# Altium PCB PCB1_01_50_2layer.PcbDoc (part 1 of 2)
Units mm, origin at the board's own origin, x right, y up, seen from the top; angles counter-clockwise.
Board outline 28.45 x 21.72 mm, 2 copper layers (Top Layer, Bottom Layer); 0 components, 1 nets, 10 pads, 74 vias.
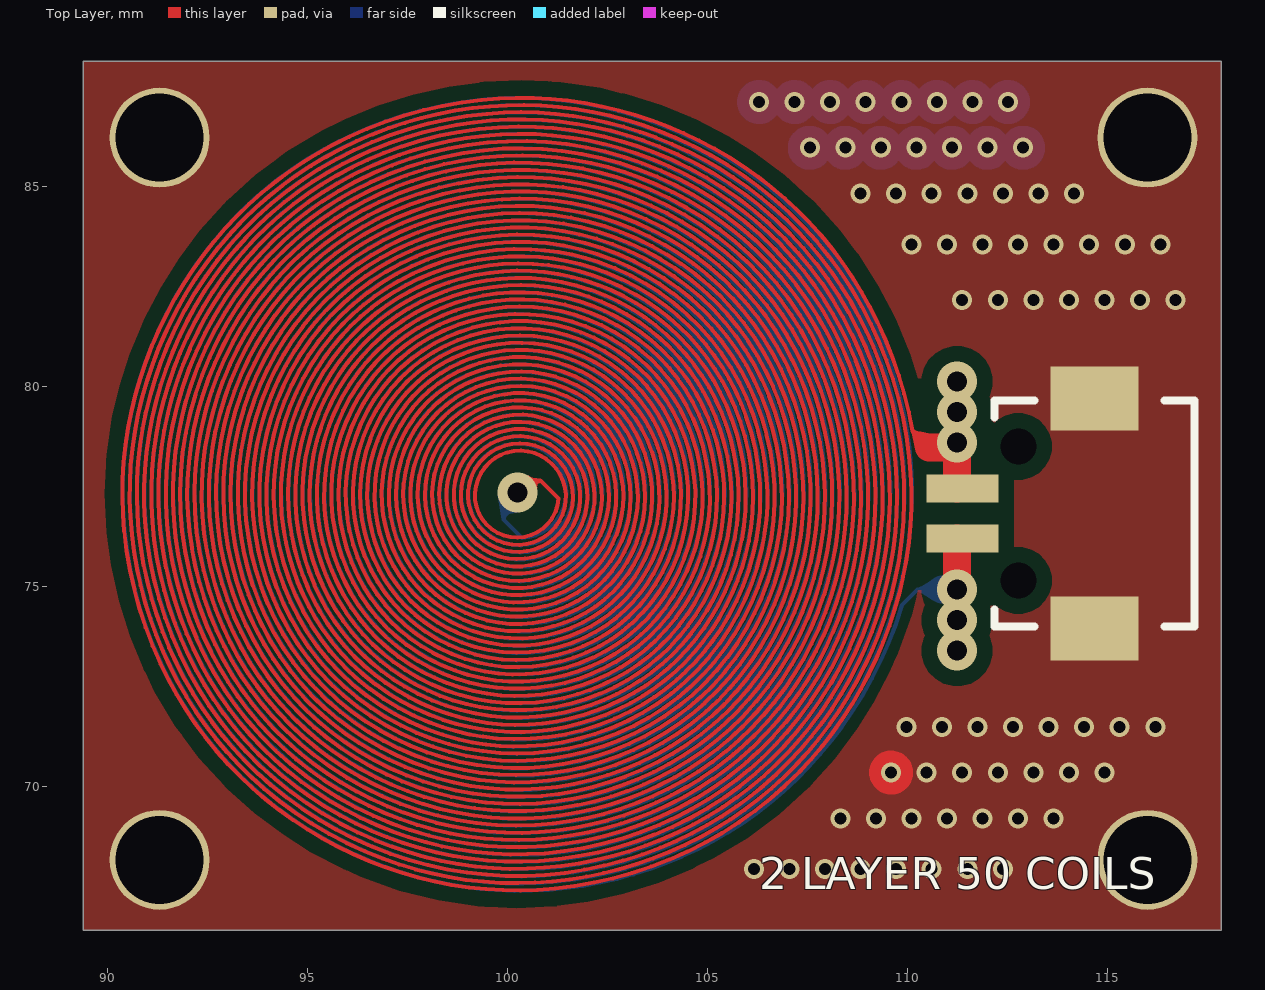
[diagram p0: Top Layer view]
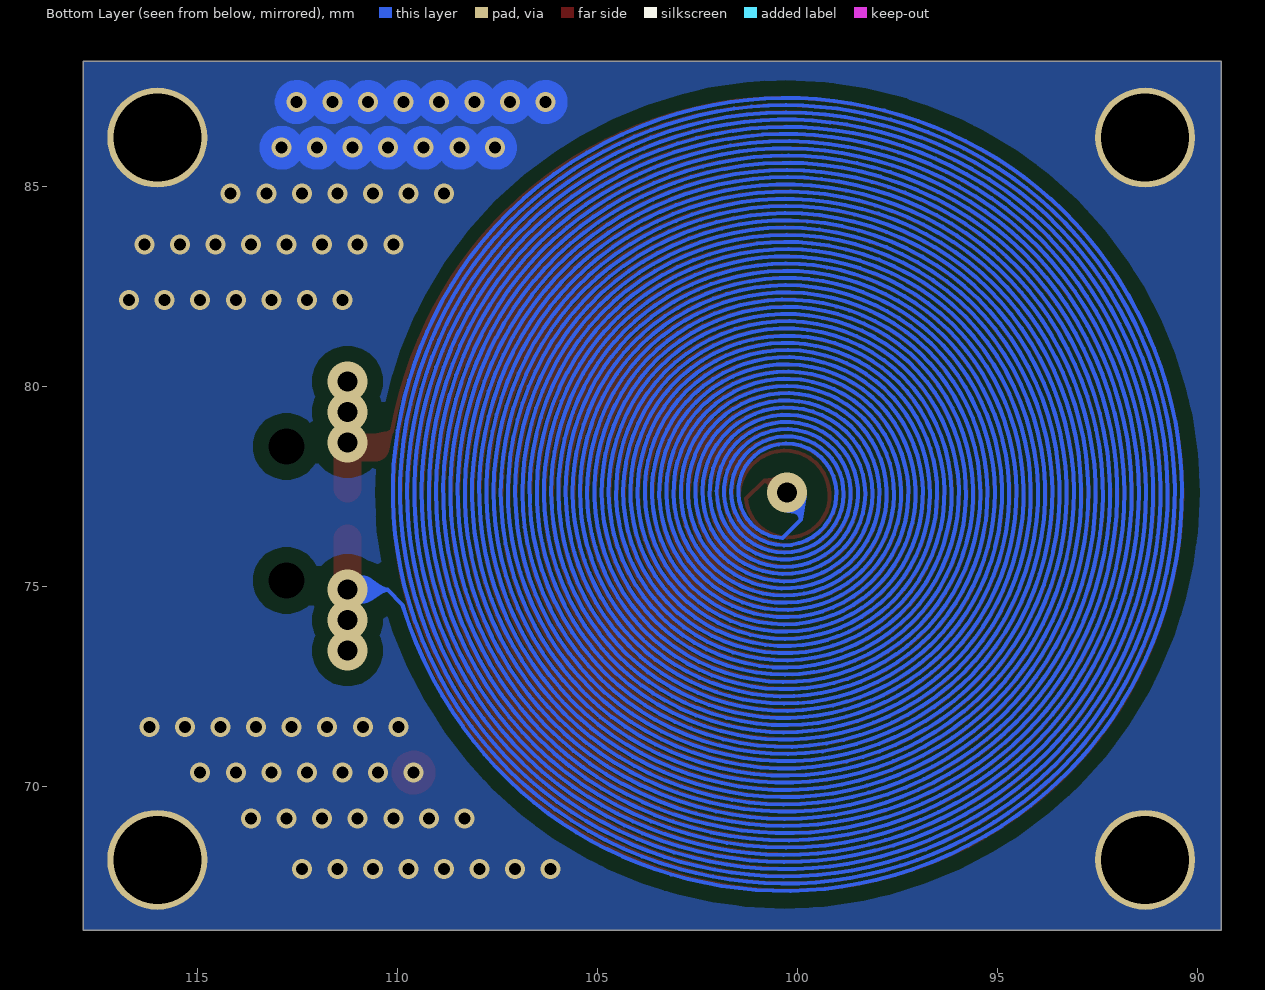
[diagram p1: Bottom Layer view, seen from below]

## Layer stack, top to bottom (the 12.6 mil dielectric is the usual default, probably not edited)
Top Solder: solder mask 0.0102, Solder Resist, Dk 3.5
Top Layer: signal copper 0.0356
Dielectric 1: dielectric 0.32, FR-4, Dk 4.8
Bottom Layer: signal copper 0.0356
Bottom Solder: solder mask 0.0102, Solder Resist, Dk 3.5

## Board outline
89.408,66.421 89.408,88.138 117.856,88.138 117.856,66.421

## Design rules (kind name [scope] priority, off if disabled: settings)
Clearance [All] p1: gap=0.381 ignorepadtopadclearanceinfootprint=FALSE
PolygonConnect [All] p1: connectstyle=Direct reliefconductorwidth=0.254 reliefentries=4 polygonreliefangle="90 Angle" airgapwidth=0.254
RoutingVias [All] p1: holewidth=0.711 width=1.27 viastyle="Through Hole" minholewidth=0.711 minwidth=1.27 maxholewidth=0.711 maxwidth=1.27
SolderMaskExpansion [All] p1: expansion=0.102 istentingtop=FALSE
Width Width_1 [All] p1: maxlimit=0.8 minlimit=0.1 preferedwidth=0.1 minimp=50.000000 maximp=50.000000 favimp=50.000000
Width [All] p2: maxlimit=0.254 minlimit=0.254 preferedwidth=0.254
30 further rules are at their usual default settings.

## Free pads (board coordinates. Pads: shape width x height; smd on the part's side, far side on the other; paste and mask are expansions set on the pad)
  round 2.5 hole 2.2: 1(91.313,68.177) 1(91.313,86.233) 1(116.008,86.233) 1(116.008,68.177)
  rect 1.8x0.7 smd: 1(111.381,77.46) 2(111.381,76.21)
  round 0.45 hole 0.9 unplated: MH1(112.781,78.51) MH2(112.781,75.16)
  rect 2.2x1.6 smd: MP1(114.681,79.71) MP2(114.681,73.96)

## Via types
v1: diameter 0.5, hole 0.3, Top Layer to Bottom Layer, tented both sides, 67 vias
v2: diameter 1, hole 0.5, Top Layer to Bottom Layer, 7 vias

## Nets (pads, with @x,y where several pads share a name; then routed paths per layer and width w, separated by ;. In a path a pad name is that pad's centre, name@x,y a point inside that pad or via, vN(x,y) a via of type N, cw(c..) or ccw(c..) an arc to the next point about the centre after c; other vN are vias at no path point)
Net1: pad.1@91.313,68.177 pad.1@91.313,86.233 pad.1@116.008,68.177 pad.1@116.008,86.233 pad.MP1 pad.MP2 | length 25.1
  Top Layer w0.6: 109.851,70.358 ccw(c109.601,70.358) 109.851,70.358
  Bottom Layer w0.6: 106.549,87.122 ccw(c106.299,87.122) 106.549,87.122 ; 107.438,87.122 ccw(c107.188,87.122) 107.438,87.122 ; 107.819,85.979 ccw(c107.569,85.979) 107.819,85.979 ; 108.327,87.122 ccw(c108.077,87.122) 108.327,87.122 ; 108.708,85.979 ccw(c108.458,85.979) 108.708,85.979 ; 109.216,87.122 ccw(c108.966,87.122) 109.216,87.122 ; 109.597,85.979 ccw(c109.347,85.979) 109.597,85.979 ; 110.105,87.122 ccw(c109.855,87.122) 110.105,87.122 ; 110.486,85.979 ccw(c110.236,85.979) 110.486,85.979 ; 110.994,87.122 ccw(c110.744,87.122) 110.994,87.122 ; 111.375,85.979 ccw(c111.125,85.979) 111.375,85.979 ; 111.883,87.122 ccw(c111.633,87.122) 111.883,87.122 ; 112.264,85.979 ccw(c112.014,85.979) 112.264,85.979 ; 112.772,87.122 ccw(c112.522,87.122) 112.772,87.122 ; 113.153,85.979 ccw(c112.903,85.979) 113.153,85.979
  other v1: 106.172,67.945 107.061,67.945 107.95,67.945 108.839,67.945 109.728,67.945 110.617,67.945 111.506,67.945 112.395,67.945 108.331,69.215 109.22,69.215 110.109,69.215 110.998,69.215 111.887,69.215 112.776,69.215 113.665,69.215 109.601,70.358 110.49,70.358 111.379,70.358 112.268,70.358 113.157,70.358 114.046,70.358 114.935,70.358 109.982,71.501 110.871,71.501 111.76,71.501 112.649,71.501 113.538,71.501 114.427,71.501 115.316,71.501 116.205,71.501 111.379,82.169 112.268,82.169 113.157,82.169 114.046,82.169 114.935,82.169 115.824,82.169 116.713,82.169 110.109,83.566 110.998,83.566 111.887,83.566 112.776,83.566 113.665,83.566 114.554,83.566 115.443,83.566 116.332,83.566 108.839,84.836 109.728,84.836 110.617,84.836 111.506,84.836 112.395,84.836 113.284,84.836 114.173,84.836 107.569,85.979 108.458,85.979 109.347,85.979 110.236,85.979 111.125,85.979 112.014,85.979 112.903,85.979 106.299,87.122 107.188,87.122 108.077,87.122 108.966,87.122 109.855,87.122 110.744,87.122 111.633,87.122 112.522,87.122
copper on no net: | length 3452.1
  Top Layer w0.1: v2(100.265,77.355) 100.563,77.653 100.843,77.653 101.289,77.207 cw(c100.244,77.281) 99.224,77.518 cw(c100.317,77.292) 100.518,78.39 cw(c100.31,77.249) 101.464,77.134 cw(c100.269,77.253) 100.309,76.052 cw(c100.267,77.293) 99.054,77.03 cw(c100.306,77.302) 99.763,78.462 cw(c100.322,77.268) 101.332,78.116 cw(c100.294,77.245) 101.43,76.506 cw(c100.261,77.266) 99.925,75.913 cw(c100.267,77.295) 98.853,77.133 cw(c100.309,77.299) 99.599,78.58 cw(c100.322,77.279) 101.227,78.461 cw(c100.296,77.244) 101.795,76.927 cw(c100.276,77.249) 100.66,75.744 cw(c100.262,77.287) 99.085,76.213 cw(c100.29,77.304) 98.75,77.824 cw(c100.306,77.303) 99.989,78.913 cw(c100.319,77.259) 101.56,78.402 cw(c100.289,77.245) 101.948,76.794 cw(c100.279,77.246) 100.801,75.598 cw(c100.259,77.272) 99.168,75.891 cw(c100.29,77.308) 98.486,77.406 cw(c100.317,77.293) 99.329,78.839 cw(c100.319,77.283) 100.986,79.002 cw(c100.325,77.266) 102.112,77.774 cw(c100.271,77.247) 100.359,75.334 cw(c100.271,77.305) 98.815,75.974 cw(c100.304,77.309) 98.321,77.573 cw(c100.318,77.291) 99.222,78.984 cw(c100.32,77.277) 100.88,79.228 cw(c100.32,77.264) 102.161,78.147 cw(c100.312,77.246) 102.217,76.471 cw(c100.289,77.235) 101.022,75.295 cw(c100.26,77.247) 99.344,75.362 cw(c100.249,77.277) 98.235,76.624 cw(c100.262,77.306) 98.367,78.299 cw(c100.293,77.318) 99.654,79.383 cw(c100.323,77.305) 101.33,79.241 cw(c100.336,77.275) 102.429,77.966 cw(c100.278,77.246) 101.102,75.133 cw(c100.262,77.286) 98.18,76.282 cw(c100.313,77.303) 100.72,79.634 cw(c100.299,77.229) 102.181,78.783 cw(c100.292,77.244) 102.101,75.61 cw(c100.26,77.274) 100.606,74.817 cw(c100.26,77.265) 98.951,75.168 cw(c100.24,77.271) 97.899,76.493 cw(c100.304,77.304) 99.008,79.486 cw(c100.326,77.257) 100.669,79.824 cw(c100.314,77.255) 102.894,77.515 cw(c100.296,77.246) 102.512,75.863 cw(c100.301,77.217) 101.203,74.787 cw(c100.26,77.285) 98.116,75.693 cw(c100.286,77.304) 98.118,78.918 cw(c100.292,77.32) 99.502,79.9 cw(c100.321,77.261) 102.566,78.872 cw(c100.298,77.245) 102.576,75.632 cw(c100.3,77.218) 101.224,74.603 cw(c100.261,77.232) 99.527,74.53 cw(c100.285,77.326) 98.088,75.439 cw(c100.33,77.32) 97.42,77.005 cw(c100.268,77.306) 97.751,78.672 cw(c100.322,77.286) 100.63,80.191 cw(c100.292,77.208) 102.199,79.527 cw(c100.328,77.269) 103.138,78.108 cw(c100.351,77.244) 103.146,76.406 cw(c100.239,77.269) 102.222,74.975 cw(c100.246,77.313) 100.665,74.28 cw(c100.257,77.228) 98.983,74.539 cw(c100.242,77.269) 97.702,75.661 cw(c100.345,77.323) 97.223,77.298 cw(c100.313,77.293) 97.696,78.936 cw(c100.324,77.281) 100.642,80.371 cw(c100.292,77.207) 102.226,79.735 cw(c100.353,77.288) 103.24,78.366 cw(c100.319,77.243) 103.395,76.669 cw(c100.28,77.248) 101.206,74.217 cw(c100.26,77.216) 99.502,74.165 cw(c100.298,77.351) 98.009,74.995 cw(c100.284,77.297) 97.155,76.472 cw(c100.217,77.306) 97.165,78.177 cw(c100.363,77.27) 98.037,79.645 cw(c100.32,77.269) 99.533,80.469 cw(c100.321,77.26) 102.701,79.552 cw(c100.285,77.246) 103.526,78.057 cw(c100.371,77.242) 103.505,76.351 cw(c100.214,77.281) 102.643,74.875 cw(c100.269,77.268) 101.166,74.018 cw(c100.26,77.203) 99.459,73.99 cw(c100.301,77.36) 97.953,74.8 cw(c100.259,77.281) 97.036,76.241 cw(c100.244,77.306) 96.925,77.945 cw(c100.379,77.264) 97.653,79.493 cw(c100.273,77.341) 99.034,80.497 cw(c100.327,77.277) 100.728,80.723 cw(c100.288,77.201) 102.324,80.109 cw(c100.293,77.239) 103.808,77.143 cw(c100.268,77.259) 103.341,75.498 cw(c100.321,77.2) 102.161,74.263 cw(c100.265,77.26) 98.852,74.007 cw(c100.267,77.304) 97.486,75.036 cw(c100.339,77.322) 96.758,76.585 cw(c100.306,77.304) 97.668,79.782 cw(c100.291,77.314) 99.101,80.714 cw(c100.326,77.296) 100.802,80.895 cw(c100.285,77.195) 102.399,80.276 cw(c100.299,77.242) 103.987,77.351 cw(c100.322,77.247) 103.636,75.677 cw(c100.274,77.24) 102.575,74.334 cw(c100.242,77.328) 101.022,73.613 cw(c100.257,77.173) 99.313,73.656 cw(c100.307,77.373) 97.798,74.457 cw(c100.22,77.252) 96.799,75.846 cw(c100.319,77.318) 96.51,77.533 cw(c100.328,77.284) 97.001,79.174 cw(c100.265,77.347) 98.156,80.436 cw(c100.349,77.196) 99.751,81.063 cw(c100.317,77.252) 102.94,80.074 cw(c100.345,77.286) 103.899,78.656 cw(c100.274,77.233) 104.159,76.963 cw(c100.247,77.268) 103.656,75.325 cw(c100.317,77.202) 102.505,74.058 cw(c100.233,77.352) 100.918,73.41 cw(c100.262,77.288) 97.697,74.306 cw(c100.207,77.24) 96.675,75.68 cw(c100.347,77.325) 96.323,77.358 cw(c100.281,77.296) 96.72,79.024 cw(c100.314,77.307) 97.774,80.375 cw(c100.333,77.235) 99.302,81.152 cw(c100.324,77.35) 101.012,81.226 cw(c100.277,77.178) 102.599,80.575 cw(c100.399,77.333) 103.771,79.328 cw(c100.302,77.248) 104.149,75.999 cw(c100.191,77.292) 103.292,74.513 cw(c100.319,77.199) 101.899,73.517 cw(c100.24,77.331) 100.219,73.172 cw(c100.268,77.254) 98.548,73.552 cw(c100.272,77.316) 97.171,74.573 cw(c100.305,77.303) 96.335,76.07 cw(c100.26,77.311) 96.17,77.776 cw(c100.358,77.272) 96.717,79.402 cw(c100.263,77.351) 97.866,80.673 cw(c100.347,77.2) 99.435,81.369 cw(c100.325,77.381) 101.148,81.384 cw(c100.272,77.168) 102.725,80.706 cw(c100.405,77.338) 103.901,79.461 cw(c100.194,77.211) 104.484,77.846 cw(c100.269,77.252) 102.289,73.506 cw(c100.228,77.372) 100.645,73.01 cw(c100.253,77.156) 98.943,73.203 cw(c100.314,77.384) 97.447,74.047 cw(c100.189,77.225) 96.405,75.407 cw(c100.38,77.335) 95.971,77.068 cw(c100.194,77.31) 96.221,78.763 cw(c100.393,77.256) 97.106,80.235 cw(c100.253,77.362) 98.492,81.242 cw(c100.349,77.193) 100.162,81.644 cw(c100.325,77.358) 101.853,81.365 cw(c100.275,77.177) 103.314,80.463 cw(c100.373,77.309) 104.311,79.068 cw(c100.21,77.216) 104.706,77.397 cw(c100.376,77.241) 104.427,75.705 cw(c100.19,77.292) 103.53,74.24 cw(c100.331,77.185) 102.144,73.233 cw(c100.231,77.363) 100.477,72.818 cw(c100.255,77.173) 98.781,73.069 cw(c100.313,77.385) 97.298,73.937 cw(c100.184,77.221) 96.258,75.299 cw(c100.391,77.338) 95.798,76.955 cw(c100.164,77.313) 95.995,78.658 cw(c100.412,77.247) 96.812,80.17 cw(c100.22,77.401) 98.132,81.263 cw(c100.319,77.257) 104.811,78.07 cw(c100.423,77.239) 104.801,76.356 cw(c100.18,77.297) 104.156,74.762 cw(c100.339,77.177) 102.981,73.513 cw(c100.236,77.35) 101.425,72.785 cw(c100.254,77.212) 99.713,72.664 cw(c100.295,77.338) 98.076,73.184 cw(c100.252,77.294) 96.733,74.253 cw(c100.3,77.296) 95.877,75.741 cw(c100.325,77.324) 95.605,77.437 cw(c100.258,77.297) 95.972,79.114 cw(c100.384,77.263) 96.911,80.553 cw(c100.25,77.364) 98.305,81.552 cw(c100.356,77.172) 99.967,81.993 cw(c100.33,77.416) 101.672,81.807 cw(c100.331,77.271) 104.978,78.151 cw(c100.417,77.239) 104.999,76.436 cw(c100.191,77.292) 104.404,74.823 cw(c100.304,77.207) 103.287,73.52 cw(c100.257,77.309) 101.776,72.701 cw(c100.243,77.295) 100.076,72.455 cw(c100.27,77.247) 98.401,72.831 cw(c100.306,77.374) 96.956,73.762 cw(c100.185,77.22) 95.935,75.141 cw(c100.406,77.344) 95.452,76.792 cw(c100.291,77.302) 96.288,80.068 cw(c100.222,77.395) 97.493,81.29 cw(c100.349,77.191) 99.052,82.016 cw(c100.331,77.317) 100.762,82.168 cw(c100.296,77.245) 102.419,81.711 cw(c100.293,77.202) 103.824,80.721 cw(c100.365,77.306) 104.795,79.306 cw(c100.183,77.208) 105.231,77.642 cw(c100.452,77.234) 105.069,75.934 cw(c100.251,77.264) 103.116,73.168 cw(c100.232,77.362) 101.555,72.447 cw(c100.25,77.236) 99.845,72.289 cw(c100.283,77.294) 98.184,72.729 cw(c100.297,77.361) 96.763,73.697 cw(c100.193,77.225) 95.76,75.09 cw(c100.411,77.346) 95.277,76.742 cw(c100.277,77.305) 96.052,80.038 cw(c100.247,77.371) 97.21,81.306 cw(c100.332,77.225) 98.731,82.107 cw(c100.342,77.243) 100.43,82.366 cw(c100.318,77.339) 102.116,82.035 cw(c100.26,77.146) 103.602,81.168 cw(c100.443,77.369) 104.711,79.859 cw(c100.168,77.202) 105.325,78.251 cw(c100.408,77.238) 105.379,76.535 cw(c100.218,77.284) 104.855,74.897 cw(c100.236,77.258) 103.83,73.517 cw(c100.318,77.21) 102.403,72.56 cw(c100.221,77.391) 100.741,72.116 cw(c100.263,77.267) 97.449,72.926 cw(c100.195,77.232) 96.177,74.08 cw(c100.331,77.31) 95.358,75.591 cw(c100.346,77.33) 95.063,77.286 cw(c100.184,77.308) 95.344,78.98 cw(c100.435,77.236) 96.155,80.498 cw(c100.192,77.429) 97.411,81.669 cw(c100.356,77.171) 98.983,82.369 cw(c100.334,77.309) 100.693,82.534 cw(c100.304,77.281) 102.363,82.13 cw(c100.266,77.156) 103.822,81.217 cw(c100.441,77.367) 104.904,79.884 cw(c100.16,77.199) 105.505,78.27 cw(c100.41,77.237) 105.563,76.554 cw(c100.229,77.282) 105.062,74.909 cw(c100.211,77.275) 104.071,73.503 cw(c100.35,77.166) 102.681,72.494 cw(c100.255,77.282) 99.323,71.996 cw(c100.312,77.378) 97.701,72.569 cw(c100.264,77.317) 96.337,73.617 cw(c100.227,77.247) 95.383,75.046 cw(c100.419,77.348) 94.919,76.704 cw(c100.254,77.307) 95.623,80.024 cw(c100.305,77.324) 96.708,81.358 cw(c100.283,77.307) 98.161,82.276 cw(c100.362,77.155) 99.828,82.703 cw(c100.321,77.297) 103.137,81.938 cw(c100.354,77.276) 104.454,80.834 cw(c100.309,77.274) 105.355,79.37 cw(c100.175,77.204) 105.768,77.699 cw(c100.309,77.246) 104.986,74.394 cw(c100.294,77.21) 103.88,73.077 cw(c100.292,77.255) 102.417,72.174 cw(c100.22,77.394) 100.747,71.755 cw(c100.261,77.249) 97.436,72.512 cw(c100.237,77.285) 96.106,73.603 cw(c100.254,77.263) 95.183,75.053 cw(c100.42,77.349) 94.737,76.716 cw(c100.247,77.308) 95.427,80.043 cw(c100.327,77.308) 96.485,81.398 cw(c100.256,77.347) 97.91,82.36 cw(c100.369,77.134) 99.56,82.853 cw(c100.33,77.46) 101.278,82.824 cw(c100.271,77.177) 102.908,82.271 cw(c100.297,77.201) 104.301,81.262 cw(c100.411,77.344) 105.317,79.876 cw(c100.252,77.231) 105.923,76.529 cw(c100.24,77.28) 105.444,74.876 cw(c100.177,77.296) 104.501,73.436 cw(c100.398,77.108) 103.17,72.35 cw(c100.214,77.41) 101.572,71.709 cw(c100.247,77.221) 99.858,71.566 cw(c100.276,77.249) 98.182,71.949 cw(c100.333,77.424) 96.688,72.807 cw(c100.117,77.159) 95.52,74.067 cw(c100.389,77.336) 94.78,75.622 cw(c100.33,77.33) 94.523,77.323 cw(c100.157,77.31) 94.789,79.021 cw(c100.357,77.274) 96.712,81.83 cw(c100.314,77.25) 98.206,82.683 cw(c100.362,77.16) 99.884,83.069 cw(c100.32,77.305) 103.202,82.316 cw(c100.325,77.237) 104.558,81.257 cw(c100.38,77.323) 105.536,79.843 cw(c100.26,77.232) 106.099,76.485 cw(c100.239,77.281) 105.622,74.832 cw(c100.165,77.302) 104.693,73.381 cw(c100.412,77.093) 103.384,72.269 cw(c100.218,77.401) 101.804,71.583 cw(c100.24,77.277) 100.096,71.374 cw(c100.261,77.171) 98.404,71.677 cw(c100.287,77.334) 95.614,73.631 cw(c100.318,77.298) 94.763,75.127 cw(c100.413,77.348) 94.367,76.803 cw(c100.243,77.307) 95.067,80.134 cw(c100.358,77.287) 96.091,81.517 cw(c100.21,77.409) 97.471,82.542 cw(c100.344,77.203) 100.805,83.248 cw(c100.303,77.296) 102.481,82.858 cw(c100.244,77.114) 103.983,82.015 cw(c100.46,77.387) 105.182,80.783 cw(c100.221,77.228) 105.977,79.256 cw(c100.194,77.207) 106.319,77.568 cw(c100.508,77.231) 106.164,75.856 cw(c100.145,77.315) 105.529,74.255 cw(c100.245,77.246) 104.478,72.892 cw(c100.359,77.159) 103.081,71.89 cw(c100.239,77.341) 99.739,71.214 cw(c100.28,77.258) 98.065,71.609 cw(c100.34,77.438) 96.561,72.45 cw(c100.123,77.164) 95.355,73.675 cw(c100.352,77.316) 94.545,75.194 cw(c100.403,77.346) 94.18,76.878 cw(c100.247,77.305) 94.902,80.207 cw(c100.367,77.281) 95.917,81.598 cw(c100.192,77.431) 97.282,82.643 cw(c100.374,77.123) 98.886,83.272 cw(c100.339,77.306) 100.599,83.441 cw(c100.317,77.364) 102.288,83.12 cw(c100.288,77.202) 105.098,81.187 cw(c100.298,77.272) 105.99,79.716 cw(c100.139,77.193) 106.452,78.055 cw(c100.491,77.234) 106.441,76.336 cw(c100.225,77.287) 105.95,74.686 cw(c100.151,77.31) 105.034,73.227 cw(c100.314,77.203) 102.204,71.328 cw(c100.226,77.357) 100.51,71.018 cw(c100.247,77.053) 98.8,71.188 cw(c100.334,77.425) 97.197,71.82 cw(c100.273,77.337) 95.821,72.856 cw(c100.142,77.181) 94.788,74.23 cw(c100.448,77.359) 94.163,75.836 cw(c100.264,77.324) 93.988,77.548 cw(c100.182,77.304) 94.293,79.241 cw(c100.382,77.261) 96.176,82.088 cw(c100.269,77.32) 97.622,83.019 cw(c100.339,77.233) 100.986,83.592 cw(c100.295,77.271) 102.656,83.176 cw(c100.239,77.104) 104.16,82.332 cw(c100.456,77.382) 105.38,81.121 cw(c100.254,77.248) 106.224,79.62 cw(c100.146,77.195) 106.647,77.95 cw(c100.517,77.233) 106.607,76.231 cw(c100.212,77.292) 106.102,74.584 cw(c100.147,77.311) 105.184,73.125 cw(c100.324,77.19) 102.373,71.195 cw(c100.219,77.384) 100.686,70.848 cw(c100.259,77.214) 97.345,71.537 cw(c100.307,77.387) 95.924,72.511 cw(c100.088,77.136) 94.817,73.827 cw(c100.417,77.346) 94.098,75.393 cw(c100.364,77.339) 93.808,77.091 cw(c100.06,77.319) 93.982,78.801 cw(c100.442,77.231) 94.602,80.409 cw(c100.375,77.278) 95.615,81.802 cw(c100.167,77.46) 96.96,82.873 cw(c100.37,77.129) 98.544,83.554 cw(c100.351,77.231) 100.247,83.806 cw(c100.334,77.482) 101.954,83.596 cw(c100.242,77.11) 103.55,82.945 cw(c100.309,77.21) 104.926,81.909 cw(c100.461,77.386) 105.975,80.547 cw(c100.136,77.192) 106.636,78.955 cw(c100.264,77.217) 106.868,77.248 cw(c100.486,77.233) 106.641,75.544 cw(c100.121,77.326) 105.978,73.952 cw(c100.233,77.252) 104.933,72.583 cw(c100.399,77.108) 103.566,71.54 cw(c100.207,77.432) 101.972,70.883 cw(c100.233,77.301) 100.266,70.652 cw(c100.25,77.077) 98.561,70.878 cw(c100.343,77.444) 96.968,71.537 cw(c100.272,77.339) 95.593,72.575 cw(c100.116,77.159) 94.541,73.935 cw(c100.445,77.357) 93.872,75.524 cw(c100.332,77.335) 93.624,77.229 cw(c100.074,77.318) 93.83,78.936 cw(c100.454,77.226) 94.468,80.538 cw(c100.373,77.28) 95.485,81.927 cw(c100.159,77.469) 96.827,83.003 cw(c100.369,77.132) 98.404,83.7 cw(c100.356,77.205) 100.103,83.983 cw(c100.337,77.52) 101.815,83.816 cw(c100.249,77.128) 103.43,83.215 cw(c100.277,77.164) 104.846,82.233 cw(c100.506,77.425) 105.958,80.921 cw(c100.171,77.207) 106.7,79.365 cw(c100.184,77.202) 107.033,77.675 cw(c100.37,77.241) 106.377,74.324 cw(c100.147,77.31) 105.444,72.875 cw(c100.444,77.059) 104.176,71.713 cw(c100.244,77.354) 102.65,70.913 cw(c100.21,77.421) 100.973,70.512 cw(c100.248,77.033) 99.254,70.548 cw(c100.304,77.333) 97.598,71.023 cw(c100.345,77.45) 96.108,71.891 cw(c100.115,77.158) 94.886,73.101 cw(c100.306,77.287) 94.013,74.586 cw(c100.467,77.364) 93.531,76.242 cw(c100.133,77.318) 93.475,77.961 cw(c100.262,77.284) 93.861,79.639 cw(c100.383,77.263) 95.786,82.465 cw(c100.246,77.351) 97.216,83.422 cw(c100.356,77.17) 100.555,84.164 cw(c100.325,77.427) 102.253,83.886 cw(c100.231,77.088) 103.834,83.197 cw(c100.318,77.219) 105.198,82.146 cw(c100.475,77.398) 106.252,80.787 cw(c100.137,77.193) 106.939,79.205 cw(c100.217,77.208) 107.223,77.505 cw(c100.556,77.228) 107.072,75.792 cw(c100.157,77.313) 106.5,74.166 cw(c100.151,77.307) 105.553,72.726 cw(c100.342,77.17) 102.759,70.762 cw(c100.206,77.433) 101.085,70.344 cw(c100.248,77.049) 99.365,70.35 cw(c100.295,77.298) 97.699,70.787 cw(c100.355,77.468) 96.184,71.611 cw(c100.158,77.205) 94.917,72.776 cw(c100.24,77.245) 93.982,74.221 cw(c100.392,77.339) 93.268,77.567 cw(c100.138,77.308) 93.548,79.265 cw(c100.48,77.214) 94.231,80.849 cw(c100.359,77.293) 95.27,82.223 cw(c100.151,77.479) 96.615,83.295 cw(c100.368,77.131) 98.185,84.009 cw(c100.364,77.169) 99.878,84.332 cw(c100.327,77.374) 103.238,83.709 cw(c100.239,77.102) 104.712,82.815 cw(c100.485,77.407) 105.924,81.594 cw(c100.276,77.264) 106.799,80.11 cw(c100.229,77.219) 107.391,76.741 cw(c100.38,77.254) 107.056,75.052 cw(c100.154,77.311) 105.255,72.142 cw(c100.41,77.097) 103.885,71.101 cw(c100.207,77.436) 102.302,70.417 cw(c100.221,77.361) 100.604,70.122 cw(c100.258,77.189) 97.251,70.784 cw(c100.341,77.444) 95.782,71.689 cw(c100.09,77.135) 94.576,72.915 cw(c100.308,77.286) 93.702,74.399 cw(c100.36,77.332) 93.098,77.768 cw(c100.185,77.299) 93.419,79.459 cw(c100.492,77.208) 94.129,81.031 cw(c100.345,77.305) 95.185,82.393 cw(c100.151,77.478) 96.536,83.457 cw(c100.369,77.127) 98.105,84.172 cw(c100.367,77.157) 99.797,84.506 cw(c100.33,77.4) 103.167,83.937 cw(c100.229,77.083) 104.663,83.079 cw(c100.448,77.369) 105.914,81.896 cw(c100.335,77.301) 106.842,80.446 cw(c100.174,77.205) 107.587,77.104 cw(c100.498,77.234) 107.347,75.4 cw(c100.114,77.331) 106.713,73.796 cw(c100.171,77.292) 105.73,72.38 cw(c100.342,77.172) 102.917,70.437 cw(c100.201,77.45) 101.247,70.003 cw(c100.247,77.078) 99.527,69.969 cw(c100.282,77.236) 97.847,70.347 cw(c100.324,77.406) 94.961,72.191 cw(c100.113,77.154) 93.925,73.565 cw(c100.455,77.36) 93.234,75.145 cw(c100.396,77.349) 92.92,76.84 cw(c100.169,77.313) 93.507,80.209 cw(c100.487,77.21) 94.364,81.707 cw(c100.204,77.426) 95.539,82.964 cw(c100.252,77.336) 96.979,83.907 cw(c100.366,77.14) 100.311,84.707 cw(c100.337,77.529) 102.019,84.507 cw(c100.242,77.118) 103.64,83.916 cw(c100.251,77.119) 105.086,82.976 cw(c100.518,77.437) 106.272,81.731 cw(c100.261,77.258) 107.135,80.239 cw(c100.209,77.213) 107.76,76.872 cw(c100.444,77.243) 107.471,75.175 cw(c100.095,77.339) 106.803,73.585 cw(c100.187,77.28) 105.797,72.185 cw(c100.339,77.179) 102.966,70.264 cw(c100.199,77.455) 101.297,69.828 cw(c100.246,77.087) 99.577,69.783 cw(c100.277,77.21) 97.892,70.141 cw(c100.336,77.427) 94.968,71.928 cw(c100.067,77.117) 93.892,73.271 cw(c100.428,77.347) 93.149,74.827 cw(c100.445,77.36) 92.769,76.509 cw(c100.037,77.32) 92.78,78.23 cw(c100.288,77.274) 93.191,79.903 cw(c100.421,77.243) 95.06,82.775 cw(c100.163,77.461) 96.432,83.814 cw(c100.375,77.112) 98.006,84.518 cw(c100.371,77.145) 99.697,84.859 cw(c100.338,77.565) 101.416,84.807 cw(c100.28,77.239) 103.081,84.361 cw(c100.271,77.163) 105.917,82.439 cw(c100.449,77.381) 106.932,81.048 cw(c100.114,77.185) 107.612,79.463 cw(c100.179,77.198) 107.929,77.768 cw(c100.596,77.227) 107.854,76.049 cw(c100.235,77.291) 107.388,74.39 cw(c100.189,77.288) 105.438,71.572 cw(c100.388,77.131) 104.04,70.568 cw(c100.199,77.457) 102.45,69.898 cw(c100.215,77.381) 100.754,69.59 cw(c100.251,77.128) 97.377,70.141 cw(c100.304,77.377) 94.56,72.092 cw(c100.144,77.175) 93.554,73.489 cw(c100.473,77.366) 92.879,75.076 cw(c100.404,77.352) 92.564,76.772 cw(c99.983,77.322) 92.636,78.491 cw(c100.341,77.259) 93.094,80.152 cw(c100.404,77.255) 95.021,82.987 cw(c100.176,77.443) 96.407,84.008 cw(c100.379,77.101) 97.987,84.701 cw(c100.372,77.144) 99.678,85.038 cw(c100.338,77.569) 101.398,84.992 cw(c100.283,77.253) 103.066,84.559 cw(c100.259,77.142) 105.934,82.682 cw(c100.495,77.417) 106.983,81.317 cw(c100.135,77.195) 107.708,79.752 cw(c100.134,77.188) 108.082,78.068 cw(c100.548,77.229) 108.077,76.347 cw(c100.318,77.271) 107.686,74.669 cw(c100.134,77.321) 105.883,71.752 cw(c100.466,77.03) 104.55,70.664 cw(c100.227,77.398) 103.007,69.894 cw(c100.197,77.46) 101.334,69.47 cw(c100.244,77.087) 99.614,69.418 cw(c100.272,77.176) 97.924,69.753 cw(c100.365,77.489) 96.343,70.444 cw(c100.296,77.381) 94.946,71.454 cw(c100.169,77.206) 92.981,74.258 cw(c100.501,77.376) 92.493,75.913 cw(c100.199,77.327) 92.37,77.631 cw(c100.092,77.311) 92.632,79.332 cw(c100.478,77.213) 93.256,80.94 cw(c100.45,77.234) 94.205,82.381 cw(c100.123,77.509) 95.441,83.578 cw(c100.285,77.279) 96.913,84.474 cw(c100.369,77.132) 100.255,85.246 cw(c100.34,77.576) 101.967,85.072 cw(c100.249,77.143) 103.604,84.53 cw(c100.223,77.07) 105.092,83.656 cw(c100.443,77.359) 106.356,82.488 cw(c100.399,77.348) 107.332,81.069 cw(c100.092,77.177) 107.985,79.471 cw(c100.183,77.197) 108.289,77.774 cw(c100.612,77.226) 108.219,76.054 cw(c100.255,77.288) 107.774,74.389 cw(c100.151,77.31) 105.902,71.516 cw(c100.453,77.046) 104.55,70.451 cw(c100.219,77.416) 102.997,69.699 cw(c100.196,77.459) 101.322,69.287 cw(c100.244,77.078) 99.601,69.239 cw(c100.271,77.167) 97.911,69.569 cw(c100.365,77.49) 96.324,70.248 cw(c100.308,77.4) 94.914,71.241 cw(c100.024,77.077) 93.753,72.512 cw(c100.33,77.293) 92.893,74.005 cw(c100.418,77.349) 92.184,77.361 cw(c100.006,77.322) 92.382,79.071 cw(c100.438,77.227) 92.94,80.703 cw(c100.495,77.207) 93.823,82.186 cw(c100.2,77.434) 94.995,83.447 cw(c100.215,77.386) 96.414,84.424 cw(c100.389,77.075) 98.008,85.083 cw(c100.372,77.153) 99.703,85.401 cw(c100.339,77.588) 101.424,85.352 cw(c100.285,77.268) 103.095,84.932 cw(c100.242,77.112) 106.007,83.118 cw(c100.556,77.468) 107.107,81.794 cw(c100.185,77.22) 107.903,80.264 cw(c100.08,77.172) 108.37,78.603 cw(c100.401,77.223) 108.481,76.884 cw(c100.499,77.237) 108.22,75.182 cw(c100.105,77.337) 107.608,73.569 cw(c100.111,77.327) 106.68,72.114 cw(c100.434,77.065) 105.472,70.888 cw(c100.333,77.216) 104.027,69.95 cw(c100.187,77.491) 102.417,69.327 cw(c100.216,77.365) 100.716,69.046 cw(c100.249,77.102) 97.332,69.579 cw(c100.333,77.427) 94.445,71.433 cw(c100.034,77.088) 93.359,72.768 cw(c100.41,77.335) 92.575,74.304 cw(c100.502,77.377) 92.118,75.968 cw(c100.172,77.326) 92.012,77.688 cw(c100.084,77.311) 92.275,79.389 cw(c100.478,77.211) 92.885,81.003 cw(c100.477,77.219) 93.808,82.461 cw(c100.156,77.477) 95.009,83.694 cw(c100.238,77.35) 96.446,84.644 cw(c100.394,77.061) 98.049,85.283 cw(c100.371,77.163) 99.747,85.585 cw(c100.34,77.603) 101.468,85.527 cw(c100.284,77.267) 103.139,85.108 cw(c100.237,77.101) 106.064,83.312 cw(c100.408,77.342) 108.006,80.489 cw(c100.176,77.202) 108.668,77.122 cw(c100.579,77.227) 108.462,75.413 cw(c100.143,77.324) 107.908,73.779 cw(c100.073,77.349) 107.039,72.288 cw(c100.354,77.139) 105.887,71.007 cw(c100.406,77.111) 104.492,69.997 cw(c100.201,77.457) 102.918,69.291 cw(c100.198,77.448) 101.234,68.913 cw(c100.243,77.04) 99.513,68.885 cw(c100.273,77.168) 97.823,69.219 cw(c100.369,77.496) 96.232,69.888 cw(c100.324,77.426) 94.806,70.86 cw(c100.037,77.089) 93.613,72.1 cw(c100.27,77.255) 92.703,73.563 cw(c100.472,77.365) 91.836,76.885 cw(c100.111,77.317) 92.369,80.27 cw(c100.46,77.224) 94.192,83.179 cw(c100.081,77.559) 95.505,84.291 cw(c100.333,77.189) 97.022,85.113 cw(c100.366,77.152) 100.387,85.787 cw(c100.34,77.586) 102.098,85.596 cw(c100.246,77.141) 103.738,85.061 cw(c100.21,77.044) 105.241,84.214 cw(c100.398,77.305) 106.544,83.086 cw(c100.502,77.425) 107.584,81.714 cw(c100.133,77.196) 108.328,80.157 cw(c100.087,77.174) 108.753,78.485 cw(c100.447,77.224) 108.836,76.764 cw(c100.488,77.241) 108.561,75.064 cw(c100.097,77.341) 107.951,73.45 cw(c100.093,77.337) 107.037,71.986 cw(c100.407,77.09) 105.852,70.737 cw(c100.375,77.156) 104.434,69.758 cw(c100.193,77.478) 102.847,69.08 cw(c100.2,77.437) 101.159,68.723 cw(c100.243,77.012) 99.438,68.711 cw(c100.276,77.178) 97.749,69.054 cw(c100.371,77.501) 96.158,69.724 cw(c100.328,77.434) 94.729,70.69 cw(c100.043,77.095) 93.525,71.92 cw(c100.245,77.239) 92.597,73.372 cw(c100.518,77.382) 91.971,74.981 cw(c100.407,77.356) 91.669,76.679 cw(c99.959,77.324) 91.714,78.4 cw(c100.266,77.274) 92.108,80.078 cw(c100.493,77.206) 93.83,83.05 cw(c100.078,77.559) 95.093,84.218 cw(c100.287,77.268) 96.57,85.108 cw(c100.383,77.091) 99.898,85.955 cw(c100.334,77.469) 103.286,85.437 cw(c100.23,77.087) 106.223,83.656 cw(c100.448,77.373) 108.229,80.876 cw(c100.121,77.187) 109.022,77.535 cw(c100.461,77.235) 108.455,74.154 cw(c100.113,77.33) 106.638,71.239 cw(c100.379,77.132) 103.837,69.262 cw(c100.205,77.437) 100.489,68.496 cw(c100.253,77.115) 97.112,69.085 cw(c100.345,77.45) 94.205,70.914 cw(c100.151,77.188) 92.233,73.719 cw(c100.455,77.361) 91.468,77.068 cw(c100.127,77.313) 92.051,80.446 cw(c100.471,77.218) 93.869,83.361 cw(c100.197,77.425) 96.662,85.349 cw(c100.38,77.101) 100.005,86.14 cw(c100.332,77.459) 103.389,85.591 cw(c100.228,77.083) 106.325,83.806 cw(c100.463,77.385) 108.352,81.041 cw(c100.102,77.181) 109.194,77.71 cw(c100.661,77.223) 109.119,75.99 cw(c100.291,77.283) 108.706,74.317 cw(c100.083,77.346) 106.978,71.347 cw(c100.506,76.987) 105.722,70.169 cw(c100.312,77.256) 104.257,69.26 cw(c100.192,77.482) 100.946,68.341 cw(c100.241,76.943) 99.225,68.372 cw(c100.285,77.214) 97.542,68.742 cw(c100.378,77.516) 95.956,69.425 cw(c100.331,77.441) 94.526,70.391 cw(c100.046,77.099) 93.312,71.611 cw(c100.21,77.214) 92.36,73.048 cw(c100.513,77.379) 91.696,74.641 cw(c100.461,77.369) 91.341,76.33 cw(c100.039,77.324) 91.314,78.052 cw(c100.144,77.298) 91.627,79.746 cw(c100.507,77.198) 92.256,81.353 cw(c100.498,77.208) 93.172,82.816 cw(c100.186,77.452) 94.347,84.075 cw(c100.172,77.44) 95.746,85.08 cw(c100.381,77.088) 97.313,85.803 cw(c100.396,77.06) 98.988,86.223 cw(c100.345,77.417) 100.708,86.319 cw(c100.333,77.537) 102.413,86.078 cw(c100.232,77.107) 104.044,85.515 cw(c100.204,77.032) 105.544,84.661 cw(c100.391,77.292) 106.855,83.542 cw(c100.554,77.468) 107.922,82.191 cw(c100.165,77.214) 108.714,80.658 cw(c100.155,77.194) 109.388,77.29 cw(c100.662,77.221) 109.232,75.575 cw(c100.205,77.307) 108.749,73.919 cw(c100.108,77.332) 106.918,71.012 cw(c100.399,77.108) 104.138,69.004 cw(c100.194,77.473) 100.808,68.151 cw(c100.239,76.907) 99.087,68.208 cw(c100.292,77.239) 97.408,68.597 cw(c100.382,77.525) 95.827,69.29 cw(c100.33,77.44) 94.401,70.261 cw(c100.042,77.096) 93.185,71.481 cw(c100.199,77.206) 92.228,72.914 cw(c100.511,77.378) 91.552,74.502 cw(c100.48,77.373) 91.177,76.187 cw(c100.078,77.326) 91.123,77.908 cw(c100.087,77.307) 91.402,79.608 cw(c100.486,77.206) 91.995,81.229 cw(c100.526,77.192) 92.873,82.715 cw(c100.247,77.398) 94.009,84.011 cw(c100.111,77.521) 95.371,85.064 cw(c100.358,77.135) 96.91,85.844 cw(c100.372,77.141) 100.282,86.507 cw(c100.345,77.654) 101.996,86.351 cw(c100.259,77.194) 103.654,85.875 cw(c100.228,77.081) 106.576,84.065 cw(c100.481,77.401) 108.621,81.311 cw(c100.075,77.172) 109.535,77.997 cw(c100.617,77.224) 109.518,76.275 cw(c100.392,77.262) 109.173,74.587 cw(c100.056,77.359) 108.523,72.988 cw(c100.086,77.339) 107.595,71.532 cw(c100.403,77.089) 106.418,70.275 cw(c100.42,77.097) 105.022,69.265 cw(c100.205,77.456) 103.461,68.529 cw(c100.181,77.509) 101.793,68.085 cw(c100.232,77.182) 100.074,67.954 cw(c100.24,76.936) 98.364,68.151 cw(c100.336,77.397) 96.716,68.663 cw(c100.344,77.451) 93.829,70.527 cw(c100.123,77.165) 91.826,73.312 cw(c100.501,77.375) 90.95,76.637 cw(c99.94,77.326) 90.983,78.358 cw(c100.208,77.283) 91.34,80.044 cw(c100.532,77.187) 91.999,81.64 cw(c100.494,77.212) 92.931,83.093 cw(c100.174,77.466) 94.111,84.348 cw(c100.16,77.454) 95.507,85.357 cw(c100.377,77.093) 97.067,86.096 cw(c100.403,77.035) 98.734,86.545 cw(c100.351,77.353) 100.451,86.686 cw(c100.344,77.633) 102.163,86.502 cw(c100.251,77.167) 103.815,86.004 cw(c100.23,77.083) 106.724,84.173 cw(c100.485,77.405) 108.769,81.418 cw(c100.065,77.169) 109.705,78.109 cw(c100.591,77.224) 109.71,76.387 cw(c100.437,77.254) 109.392,74.694 cw(c100.07,77.354) 108.772,73.083 cw(c100.059,77.355) 107.877,71.606 cw(c100.35,77.136) 106.733,70.318 cw(c100.476,77.023) 105.369,69.266 cw(c100.227,77.413) 103.833,68.48 cw(c100.204,77.432) 100.469,67.775 cw(c100.25,77.073) 97.083,68.329 cw(c100.373,77.504) 94.101,70.042 cw(c100.021,77.077) 92.893,71.27 cw(c100.194,77.2) 91.934,72.701 cw(c100.513,77.378) 91.245,74.284 cw(c100.507,77.381) 90.844,75.963 cw(c100.136,77.33) 90.751,77.684 cw(c99.991,77.32) 90.978,79.391 cw(c100.439,77.22) 91.512,81.032 cw(c100.465,77.225) 93.395,83.908 cw(c100.174,77.451) 96.177,85.917 cw(c100.397,77.05) 99.493,86.828 cw(c100.342,77.59) 101.215,86.826 cw(c100.311,77.419) 102.908,86.505 cw(c100.21,77.052) 104.52,85.887 cw(c100.207,77.036) 106,84.998 cw(c100.419,77.321) 107.296,83.862 cw(c100.565,77.478) 108.36,82.508 cw(c100.17,77.219) 109.164,80.981 cw(c100.11,77.181) 109.919,77.627 cw(c100.538,77.228) 109.436,74.23 cw(c100.029,77.372) 108.749,72.646 cw(c100.099,77.329) 107.797,71.206 cw(c100.431,77.061) 106.606,69.961 cw(c100.421,77.099) 105.207,68.957 cw(c100.204,77.46) 103.648,68.215 cw(c100.175,77.527) 101.984,67.754 cw(c100.227,77.226) 100.268,67.593 cw(c100.235,76.872) 98.553,67.746 cw(c100.32,77.34) 96.891,68.207 cw(c100.371,77.501) 93.928,69.954 cw(c100.004,77.062) 92.727,71.188 cw(c100.199,77.202) 91.772,72.622 cw(c100.517,77.379) 91.081,74.205 cw(c100.516,77.383) 90.674,75.883 cw(c100.155,77.332) 90.568,77.603 cw(c99.954,77.324) 90.777,79.312 cw(c100.417,77.227) 91.287,80.96 cw(c100.491,77.209) 93.117,83.872 cw(c100.04,77.604) 94.385,85.037 cw(c100.258,77.305) 95.845,85.953 cw(c100.406,77.025) 97.445,86.603 cw(c100.393,77.08) 99.132,86.969 cw(c100.345,77.482) 100.853,87.033 cw(c100.331,77.544) 102.558,86.783 cw(c100.23,77.108) 104.194,86.235 cw(c100.241,77.098) 107.067,84.345 cw(c100.483,77.404) 109.093,81.575 cw(c100.05,77.164) 110.05,78.271 cw(c100.552,77.222) 110.084,76.549 cw(c100.512,77.242) 109.806,74.849 cw(c100.101,77.344) 109.234,73.22 cw(c100.023,77.375) 108.392,71.712 cw(c100.262,77.209) 107.305,70.374 cw(c100.405,77.105) 104.509,68.383 cw(c100.182,77.51) 101.194,67.46 cw(c100.239,76.982) 99.472,67.443 cw(c100.263,77.079) 97.774,67.737 cw(c100.365,77.478) 96.15,68.322 cw(c100.39,77.54) 94.648,69.174 cw(c100.215,77.292) 93.317,70.27 cw(c99.953,77.017) 92.205,71.584 cw(c100.338,77.288) 91.341,73.076 cw(c100.525,77.383) 90.429,76.394 cw(c99.992,77.327) 90.416,78.116 cw(c100.103,77.302) 90.713,79.814 cw(c100.497,77.2) 91.299,81.438 cw(c100.554,77.178) 92.151,82.94 cw(c100.3,77.357) 93.246,84.272 cw(c100.017,77.627) 94.558,85.386 cw(c100.295,77.231) 96.048,86.252 cw(c100.409,77.003) 99.363,87.175 cw(c100.356,77.498) 101.085,87.198 cw(c100.338,77.459) 102.784,86.916 cw(c100.256,77.132) 104.412,86.343 cw(c100.252,77.113) 105.92,85.502 cw(c100.424,77.362) 107.26,84.414 cw(c100.662,77.615) 108.386,83.101 cw(c100.113,77.225) 109.267,81.604 cw(c99.857,77.09) 110.135,78.902 110.551,78.486 ; v2@111.252,78.294 v2(111.252,78.613)
  Top Layer w0.7: 110.551,78.486 111.125,78.486 v2(111.252,78.613) ; v2(111.252,74.93) 111.252,76.21 ; 111.252,77.46 v2@111.252,78.294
